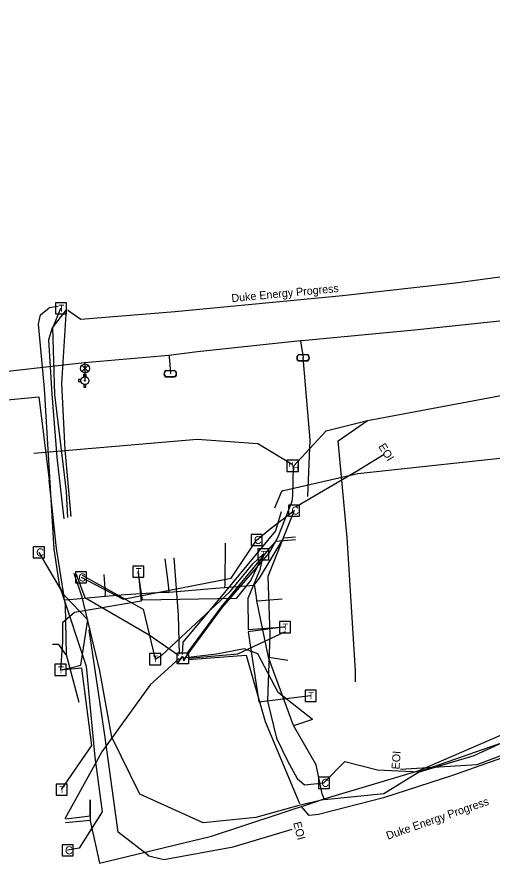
# Model space of a CAD drawing. Extents: x 2070721 to 2083039, y 729290 to 737883.
# Drawn here: x 2079795.9 to 2080033.2, y 734847.8 to 735270.6 of the extents above; entities that cross this region are included whole.
import ezdxf

# ---------------------------------------------------------------- set-up
doc = ezdxf.new("R2010")
doc.units = 0
for name, color, linetype in [('Cogo Default Point CELL', 7, 'Continuous'), ('COGO Default Point Elevation', 7, 'Continuous'), ('COGO Default Point Number', 7, 'Continuous'), ('Exist Utilities Telephone UG Cable SUE LOS C Cogo Comment', 7, 'Continuous'), ('Exist Utilities Telephone UG Cable SUE LOS C Cogo Elevation', 7, 'Continuous'), ('Exist Utilities Telephone UG Cable SUE LOS C Cogo Number', 7, 'Continuous'), ('Exist Utilities Telephone UG FO Cogo Point CELL', 7, 'Continuous'), ('Exist Utilities Telephone UG FO SUE LOS B Cogo Comment', 7, 'Continuous'), ('Exist Utilities TV Pedestal Cogo Elevation', 7, 'Continuous'), ('Exist Utilities TV Pedestal Cogo Number', 7, 'Continuous'), ('Exist Utilities TV UG Cable Cogo Point CELL', 7, 'Continuous'), ('Exist Utilities TV UG Cable SUE LOS C Cogo Comment', 7, 'Continuous'), ('Exist Utilities TV UG Cable SUE LOS C Cogo Elevation', 7, 'Continuous'), ('Exist Utilities TV UG FO Cable SUE LOS B Cogo Comment', 7, 'Continuous'), ('Exist Utilities TV UG FO Cable SUE LOS B Cogo Number', 7, 'Continuous'), ('Exist Utilities Water Meter CELL', 7, 'Continuous')]:
    doc.layers.add(name, color=color, linetype=linetype)

msp = doc.modelspace()

# ---------------------------------------------------------------- linework, layer by layer
at = {"layer": 'Cogo Default Point CELL'}
for p, q in [((2079934.29, 735023.96), (2079934.29, 735023.96)), ((2079915.6, 735009.28), (2079915.6, 735009.28)), ((2079806.81, 735003.04), (2079806.81, 735003.04)), ((2079827.88, 734990.55), (2079827.88, 734990.55)), ((2079949.27, 734887.92), (2079949.27, 734887.92)), ((2079821.23, 734854.21), (2079821.23, 734854.21))]:
    msp.add_line(p, q, dxfattribs=at)
for points in [[(2079931.51, 735021.19), (2079937.06, 735021.19), (2079937.06, 735026.74), (2079931.51, 735026.74), (2079931.51, 735021.19)], [(2079912.83, 735006.51), (2079918.38, 735006.51), (2079918.38, 735012.06), (2079912.83, 735012.06), (2079912.83, 735006.51)], [(2079804.04, 735000.27), (2079809.59, 735000.27), (2079809.59, 735005.82), (2079804.04, 735005.82), (2079804.04, 735000.27)], [(2079825.1, 734987.78), (2079830.65, 734987.78), (2079830.65, 734993.33), (2079825.1, 734993.33), (2079825.1, 734987.78)], [(2079946.5, 734885.15), (2079952.05, 734885.15), (2079952.05, 734890.7), (2079946.5, 734890.7), (2079946.5, 734885.15)], [(2079818.46, 734851.44), (2079824.01, 734851.44), (2079824.01, 734856.99), (2079818.46, 734856.99), (2079818.46, 734851.44)]]:
    msp.add_lwpolyline(points, dxfattribs=at)
at = {"layer": 'COGO Default Point Elevation'}
msp.add_lwpolyline([(2079831.51, 735096.55), (2079828.36, 735093.4), (2079829.93, 735094.97), (2079831.51, 735093.4), (2079828.36, 735096.55)], dxfattribs=at)
msp.add_circle((2079829.93, 735094.97), 2.23, dxfattribs=at)
at = {"layer": 'COGO Default Point Number'}
msp.add_line((2079829.83, 735088.89), (2079829.83, 735088.89), dxfattribs=at)
for points in [[(2079829.32, 735090.81), (2079829.32, 735092.09), (2079830.34, 735092.09), (2079830.34, 735090.78)], [(2079827.92, 735089.41), (2079826.63, 735089.41), (2079826.63, 735088.38), (2079827.92, 735088.38)], [(2079829.32, 735086.98), (2079829.32, 735085.69), (2079830.34, 735085.69), (2079830.34, 735087.01)]]:
    msp.add_lwpolyline(points, dxfattribs=at)
for radius in [1.98, 0.243]:
    msp.add_circle((2079829.83, 735088.89), radius, dxfattribs=at)
at = {"layer": 'Exist Utilities Telephone UG Cable SUE LOS C Cogo Comment'}
for points in [[(2079964.93, 734938.4), (2079964.93, 734943.9), (2079960.87, 735010.33), (2079956.41, 735058.83), (2079970.93, 735068.94)], [(2079861.84, 734851.44), (2079846.5, 734863.35), (2079839.82, 734911.79), (2079832.04, 734964.37)], [(2079861.04, 734851.58), (2079869.33, 734849.63), (2079903.86, 734856.01), (2079933.32, 734864.79)]]:
    msp.add_lwpolyline(points, dxfattribs=at)
at = {"layer": 'Exist Utilities Telephone UG Cable SUE LOS C Cogo Elevation'}
msp.add_line((2079933.68, 735046.14), (2079933.68, 735046.14), dxfattribs=at)
msp.add_lwpolyline([(2079930.73, 735043.41), (2079936.48, 735043.41), (2079936.48, 735049.16), (2079930.73, 735049.16), (2079930.73, 735043.41)], dxfattribs=at)
at = {"layer": 'Exist Utilities Telephone UG Cable SUE LOS C Cogo Number'}
msp.add_line((2079878.82, 734950.25), (2079878.82, 734950.25), dxfattribs=at)
msp.add_lwpolyline([(2079875.97, 734952.87), (2079881.52, 734952.87), (2079881.52, 734947.31), (2079875.97, 734947.31)], close=True, dxfattribs=at)
for points in [[(2079875.97, 734947.31), (2079878.61, 734951.26), (2079879.24, 734949.05), (2079881.52, 734952.87)], [(2079876.04, 734947.31), (2079878.61, 734951.05), (2079879.2, 734948.87), (2079881.52, 734952.71)]]:
    msp.add_lwpolyline(points, dxfattribs=at)
at = {"layer": 'Exist Utilities Telephone UG FO Cogo Point CELL'}
for p, q in [((2079938.82, 735100.31), (2079938.82, 735100.31)), ((2079872.5, 735092.31), (2079872.5, 735092.31))]:
    msp.add_line(p, q, dxfattribs=at)
for points in [[(2079940.86, 735098.75), (2079936.76, 735098.75)], [(2079940.86, 735098.61), (2079936.76, 735098.61)], [(2079936.78, 735102.01), (2079940.86, 735102.01)], [(2079936.78, 735101.88), (2079940.86, 735101.88)], [(2079874.54, 735090.75), (2079870.44, 735090.75)], [(2079874.54, 735090.61), (2079870.44, 735090.61)], [(2079870.46, 735094.01), (2079874.54, 735094.01)], [(2079870.46, 735093.87), (2079874.54, 735093.87)]]:
    msp.add_lwpolyline(points, dxfattribs=at)
for centre, radius, start, end in [((2079937.51, 735100.31), 1.86, 113.178, 245.9794), ((2079937.53, 735100.31), 1.73, 115.3009, 243.7824), ((2079940.11, 735100.31), 1.86, 293.6483, 66.3084), ((2079940.13, 735100.31), 1.73, 295.1272, 64.8728), ((2079871.19, 735092.3), 1.86, 113.178, 245.9794), ((2079871.21, 735092.3), 1.73, 115.3009, 243.7824), ((2079873.79, 735092.31), 1.86, 293.6483, 66.3084), ((2079873.81, 735092.31), 1.73, 295.1272, 64.8728)]:
    msp.add_arc(centre, radius, start, end, dxfattribs=at)
at = {"layer": 'Exist Utilities Telephone UG FO SUE LOS B Cogo Comment'}
for p, q in [((2079817.84, 735125.07), (2079817.84, 735125.07)), ((2079918.9, 735002.11), (2079918.9, 735002.11)), ((2079856.43, 734993.49), (2079856.43, 734993.49)), ((2079929.7, 734965.76), (2079929.7, 734965.76)), ((2079864.91, 734949.77), (2079864.91, 734949.77)), ((2079817.61, 734944.38), (2079817.61, 734944.38)), ((2079942.5, 734931.41), (2079942.5, 734931.41)), ((2079818.16, 734884.53), (2079818.16, 734884.53))]:
    msp.add_line(p, q, dxfattribs=at)
for points in [[(2079815.11, 735122.24), (2079820.71, 735122.24), (2079820.71, 735127.84), (2079815.11, 735127.84), (2079815.11, 735122.24)], [(2079916.18, 734999.28), (2079921.77, 734999.28), (2079921.77, 735004.88), (2079916.18, 735004.88), (2079916.18, 734999.28)], [(2079853.7, 734990.67), (2079859.3, 734990.67), (2079859.3, 734996.26), (2079853.7, 734996.26), (2079853.7, 734990.67)], [(2079926.98, 734962.94), (2079932.57, 734962.94), (2079932.57, 734968.53), (2079926.98, 734968.53), (2079926.98, 734962.94)], [(2079862.18, 734946.95), (2079867.78, 734946.95), (2079867.78, 734952.54), (2079862.18, 734952.54), (2079862.18, 734946.95)], [(2079814.88, 734941.56), (2079820.48, 734941.56), (2079820.48, 734947.15), (2079814.88, 734947.15), (2079814.88, 734941.56)], [(2079939.78, 734928.58), (2079945.37, 734928.58), (2079945.37, 734934.18), (2079939.78, 734934.18), (2079939.78, 734928.58)], [(2079815.44, 734881.71), (2079821.03, 734881.71), (2079821.03, 734887.3), (2079815.44, 734887.3), (2079815.44, 734881.71)]]:
    msp.add_lwpolyline(points, dxfattribs=at)
at = {"layer": 'Exist Utilities TV Pedestal Cogo Elevation'}
for points in [[(2079937.59, 735108.95), (2079940.07, 735109.15), (2079994.44, 735114.29), (2080071.74, 735122.47)], [(2079871.83, 735101.56), (2079886, 735103.41), (2079937.59, 735108.95)], [(2079937.59, 735108.95), (2079937.93, 735106.67), (2079938.88, 735100.36)], [(2079829.56, 735097.92), (2079871.83, 735101.56)], [(2079871.83, 735101.56), (2079872.06, 735099.08), (2079872.67, 735092.35)], [(2079941.2, 735030.98), (2079942.38, 735059.26), (2079938.88, 735100.36)], [(2079782.41, 735092.68), (2079823.71, 735097.22), (2079829.56, 735097.92)], [(2079829.56, 735097.92), (2079829.76, 735095.55), (2079829.87, 735094.94), (2079829.86, 735088.82)]]:
    msp.add_lwpolyline(points, dxfattribs=at)
at = {"layer": 'Exist Utilities TV Pedestal Cogo Number'}
for p, q in [((2079820.55, 734952.02), (2079826.75, 734928.16)), ((2079943.49, 734919.53), (2079934, 734916.34))]:
    msp.add_line(p, q, dxfattribs=at)
for points in [[(2079414.85, 735046.76), (2079454.13, 735049.75), (2079543.65, 735057.22), (2079599.14, 735062.31), (2079679.58, 735068.56), (2079761.05, 735076.49), (2079806.84, 735080.78), (2079812.03, 735039.09)], [(2079819.7, 734979.23), (2079819.1, 734983), (2079815.63, 735004.94), (2079812.03, 735039.09)], [(2079914.14, 734986.5), (2079917.04, 734990.19), (2079929.28, 735010.34), (2079935.11, 735010.83)], [(2079899.81, 734985.29), (2079899.84, 734986.97), (2079900.15, 735007.66)], [(2079871.98, 734983.03), (2079871.52, 734986.88), (2079869.95, 734999.87)], [(2079840.03, 734981.01), (2079840.09, 734982.77), (2079839.39, 734992.02)], [(2079899.81, 734985.29), (2079895.09, 734985.08), (2079871.98, 734983.03)], [(2079914.14, 734986.5), (2079899.81, 734985.29)], [(2079915.7, 734978.81), (2079915.49, 734980.72), (2079914.64, 734986.24), (2079914.14, 734986.5)], [(2079840.03, 734981.01), (2079823.9, 734979.6), (2079819.7, 734979.23)], [(2079871.98, 734983.03), (2079868.44, 734983.01), (2079849.88, 734981.79), (2079840.03, 734981.01)], [(2079819.7, 734979.23), (2079819.99, 734976.46), (2079820.55, 734952.02)], [(2079915.7, 734978.81), (2079918.01, 734979), (2079928.3, 734979.85)], [(2079921.53, 734950.78), (2079915.7, 734978.81)], [(2079820.54, 734951.86), (2079816.8, 734957.12), (2079813.68, 734957.12)], [(2079921.53, 734950.78), (2079923.85, 734950.38), (2079931.17, 734949.3)], [(2079949.32, 734879.97), (2079948.37, 734882.46), (2079945.4, 734896.93), (2079933.99, 734916.54), (2079922.96, 734946.84), (2079921.53, 734950.78)], [(2079949.32, 734879.97), (2079996.84, 734894.02), (2080044.13, 734914.6), (2080077.42, 734926.53), (2080123.41, 734941.95), (2080133.94, 734945)], [(2079820.34, 734869.93), (2079832.43, 734871.42), (2079832.43, 734879.38), (2079832.53, 734869.03), (2079820.22, 734867.89)], [(2079837.08, 734847.83), (2079893.1, 734861.27), (2079943.95, 734878.14), (2079949.32, 734879.97)], [(2079832.45, 734868.87), (2079835.42, 734855.37)], [(2079835.42, 734855.37), (2079836.25, 734851.6), (2079837.08, 734847.83)]]:
    msp.add_lwpolyline(points, dxfattribs=at)
at = {"layer": 'Exist Utilities TV UG Cable Cogo Point CELL'}
msp.add_line((2079816.51, 735126), (2079811.96, 735125.25), dxfattribs=at)
for points in [[(2079817.61, 734944.38), (2079822.67, 734945.46), (2079827.77, 734946.69), (2079831.29, 734969.34), (2079819.71, 734981.48), (2079817.33, 734985.82), (2079814.49, 735004.64), (2079809.64, 735084.95), (2079806.69, 735117.1), (2079807.59, 735121.72), (2079811.96, 735125.25)], [(2079821.27, 735020.53), (2079820.66, 735033.5), (2079814.75, 735081.99), (2079813.89, 735115.23), (2079817.83, 735125.07)], [(2079918.9, 735002.11), (2079912.79, 734989.12), (2079905.4, 734980.06), (2079858.58, 734979.14), (2079856.42, 734993.56), (2079857.94, 734978.69), (2079836.42, 734975.05), (2079824.67, 734973.1), (2079818.6, 734967.8), (2079818.6, 734958.21), (2079817.61, 734944.38)], [(2079828.5, 734991.62), (2079858.93, 734974.65), (2079864.89, 734949.65), (2079868.05, 734951.56), (2079902.35, 734983.45), (2079913.68, 734997.32), (2079918.9, 735002.14), (2079917.23, 734994.34), (2079911.29, 734979.95), (2079911.33, 734964.51), (2079929.81, 734965.81), (2079911.43, 734963.36), (2079916.73, 734928.46), (2079942.45, 734931.48)], [(2079818.15, 734884.62), (2079833.35, 734906.59), (2079828.26, 734945.18), (2079817.57, 734944.24)]]:
    msp.add_lwpolyline(points, dxfattribs=at)
at = {"layer": 'Exist Utilities TV UG Cable SUE LOS C Cogo Comment'}
for points in [[(2079821.33, 735124.13), (2079827.86, 735119.63), (2079874.94, 735123.38), (2079958.5, 735131.34), (2080015, 735137.74), (2080088.94, 735147.78), (2080173.89, 735156.26), (2080200.11, 735169.56), (2080228.49, 735215.43), (2080246.93, 735270.61)], [(2079820.82, 735124.7), (2079813.52, 735115.34), (2079811.73, 735109.27), (2079813.4, 735082.17), (2079815.83, 735050.61), (2079819.25, 735019.8)], [(2079823, 735021), (2079819.99, 735054.23), (2079818.26, 735087.39), (2079820.67, 735124.76)], [(2079970.93, 735068.94), (2080060.68, 735085.85), (2080105.85, 735089.11), (2080166.83, 735095.38), (2080172.93, 735082.78)], [(2079933.65, 735031.31), (2079934.01, 735046.2), (2079950.34, 735063.83), (2079970.93, 735068.94)], [(2079929, 735034.01), (2079966.1, 735042.55), (2080052.65, 735051.87), (2080116.2, 735063.66), (2080127.54, 735054.13)], [(2079933.36, 735046.91), (2079916.26, 735057.31), (2079885.92, 735059.47), (2079804.25, 735052.53)], [(2079880.87, 734951.79), (2079898.59, 734975.74), (2079921.87, 735002.72), (2079926.41, 735010.81), (2079933.42, 735028.58), (2079933.65, 735031.31)], [(2079929, 735034.01), (2079928.11, 735033.48), (2079924.48, 735025.08)], [(2079927.87, 735023.3), (2079924.98, 735013.79), (2079896.42, 734979.23), (2079878.78, 734958.14), (2079878.49, 734952.06)], [(2079935.01, 735009.41), (2079924.98, 735008.45), (2079921.43, 735004.31), (2079897.96, 734975.94), (2079880.59, 734952.34)], [(2079877.01, 734952.22), (2079876.67, 734971.65), (2079874.43, 735000.27)], [(2079949.54, 734879.56), (2079936.72, 734876.68), (2079915.26, 734870.54), (2079888.89, 734867.91), (2079857.32, 734882.19), (2079843.23, 734910.76), (2079837.34, 734943.81), (2079828.44, 734980.63), (2079824.51, 734992.48)], [(2079825.39, 734992.25), (2079829.74, 734980.55), (2079861.87, 734961.95), (2079876.65, 734951.77)], [(2079881.57, 734950.14), (2079906.31, 734952.42), (2079930.02, 734963.54)], [(2079943.45, 734919.54), (2079926.4, 734933.05), (2079916.15, 734952.37), (2079909.35, 734954.83), (2079895.57, 734952.25), (2079878.82, 734950.25)], [(2079881.41, 734949.51), (2079910.44, 734951.78), (2079919.8, 734918.62), (2079937.05, 734877.55)], [(2079876.86, 734950.12), (2079862.49, 734936.96), (2079838.26, 734903.35), (2079819.82, 734869.91)], [(2079949.54, 734879.56), (2079979.11, 734882.53), (2079996.9, 734893.62), (2080046.16, 734910.81), (2080070.87, 734920.4), (2080091.91, 734922.1), (2080094.14, 734922.76), (2080121.97, 734932.67), (2080134.03, 734940.16), (2080135.53, 734941.3), (2080137.12, 734943.43), (2080137.09, 734946.33)], [(2079987.46, 734894.8), (2080025.82, 734897.12), (2080069.48, 734913.65), (2080069.5, 734913.41), (2080092.72, 734923.35), (2080113.03, 734931.23), (2080133.81, 734940.47), (2080134.5, 734941.28), (2080135.67, 734943.18), (2080136.32, 734946.38)], [(2080070.67, 734913.66), (2080046.49, 734903.28), (2080013.44, 734891.52), (2079979.04, 734880.46), (2079946.47, 734872.13), (2079941.84, 734871.56), (2079937.96, 734876.06)]]:
    msp.add_lwpolyline(points, dxfattribs=at)
at = {"layer": 'Exist Utilities TV UG Cable SUE LOS C Cogo Elevation'}
for points in [[(2079935.37, 735026.02), (2079965.55, 735043.69), (2079979.35, 735052.1)], [(2079827.95, 734990.62), (2079849.02, 734979.74), (2079902.83, 734990.26), (2079915.57, 735009.2), (2079922.31, 735014.82), (2079934.31, 735023.97), (2079921.14, 734991.04), (2079922.13, 734961.81), (2079921.05, 734928.69), (2079925.47, 734910.25), (2079931.06, 734898.98), (2079935.82, 734890.03), (2079939.57, 734887), (2079949.27, 734887.92)], [(2079806.9, 735003.08), (2079817.75, 734984.43), (2079830.39, 734946.28), (2079834.72, 734900.79), (2079838.43, 734873.38), (2079826.93, 734855.34), (2079821.22, 734854.31)], [(2079949.24, 734887.87), (2079959.74, 734898.59), (2079975.94, 734894.45), (2079996.9, 734893.38), (2080024.24, 734901.56), (2080063.46, 734919.58), (2080075.63, 734929.35), (2080104.34, 734945.04), (2080121.88, 734961.24)]]:
    msp.add_lwpolyline(points, dxfattribs=at)

# ---------------------------------------------------------------- texts
at = {"layer": 'Cogo Default Point CELL'}
for p in [(2079932.98, 735021.96), (2079914.3, 735007.28), (2079805.51, 735001.04), (2079826.57, 734988.55), (2079947.96, 734885.92), (2079819.92, 734852.21)]:
    msp.add_text('C', height=4, dxfattribs=at).set_placement(p)
at = {"layer": 'Exist Utilities Telephone UG Cable SUE LOS C Cogo Elevation'}
for p in [(2079931.52, 735045.66), (2079934.09, 735044.14)]:
    msp.add_text('H', height=2.5, dxfattribs=at).set_placement(p)
at = {"layer": 'Exist Utilities Telephone UG FO SUE LOS B Cogo Comment'}
for p in [(2079816.71, 735123.36), (2079917.77, 735000.4), (2079855.3, 734991.78), (2079928.57, 734964.05), (2079863.78, 734948.06), (2079816.47, 734942.67), (2079941.37, 734929.7), (2079817.03, 734882.82)]:
    msp.add_text('T', height=3.42, dxfattribs=at).set_placement(p)
at = {"layer": 'Exist Utilities TV UG FO Cable SUE LOS B Cogo Comment'}
for rotation, p in [(85.478, (2079986.93, 734894.53)), (284.6363, (2079933.84, 734867.94))]:
    msp.add_text('EOI', height=4, rotation=rotation, dxfattribs=at).set_placement(p)
at = {"layer": 'Exist Utilities TV UG FO Cable SUE LOS B Cogo Number'}
msp.add_text('EOI', height=4, rotation=301.8516, dxfattribs=at).set_placement((2079976.26, 735056.04))
at = {"layer": 'Exist Utilities Water Meter CELL'}
for rotation, p in [(5.4439, (2079903.22, 735128.08)), (19.0961, (2079981.14, 734859.48))]:
    msp.add_text('Duke Energy Progress', height=4, rotation=rotation, dxfattribs=at).set_placement(p)

doc.saveas('drawing.dxf')
